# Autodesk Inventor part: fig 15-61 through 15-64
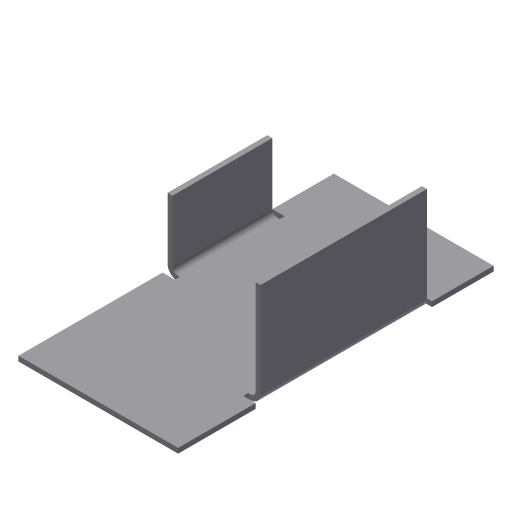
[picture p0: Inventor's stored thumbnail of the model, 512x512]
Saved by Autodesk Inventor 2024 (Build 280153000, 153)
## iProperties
Shininess: 77.0
Angle Display Precision: 2
Document Length Units: 11269
Document Angle Units: 11279
Document Time Units: 11290
Document Mass Units: 11283
Document Length Units Precision: 3
Document Angle Units Precision: 2
Compacted: True
Created: 2002-04
Part Number: fig 15-61 through 15-64
Document SubType Name: Sheet Metal
Density: 1 g/cm^3
Sheet Metal Rule: Default
Material: Generic
Appearance: Default
Density: 0.0
Volumn: 0.0
Area: 0.0
PropertySet Name: Model Information
Control State: 0
Master: False
Checked Out: False
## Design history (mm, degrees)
node "Face1"
  sketch "Sketch1"
    geometry: L1 (-33.176, 5.765)-(14.235, 5.765); L2 (14.235, 5.765)-(14.235, -18.235); L3 (14.235, -18.235)-(-33.176, -18.235); L4 (-33.176, -18.235)-(-33.176, 5.765)
    constraints: 8 end point, 2 parallel, 1 horizontal, 1 perpendicular
node "Flange1"
node "Flange2"
body "Solid1"
face "Plate1" dims "d24" = 0.75 (= Thickness)
sketch "Sketch2"
  geometry: L1 (37.412, 0)-(22.412, 0); L2 (22.412, 0)-(22.412, 10); L3 (22.412, 10)-(37.412, 10); L4 (37.412, 10)-(37.412, 0)
  constraints: 8 end point
face "Plate2" dims "d1" = 10, "d2" = 15, "d4" = 10, "d5" = 90 deg, "d6" = 0.75 (= BendRadius), "d24" = 0.75 (= Thickness), "MinimumRemnant" = 1.5 (= 2 x Thickness), "BendReliefWidth" = 0.75 (= Thickness)
bend "Bend1" dims "d3" = 0.75 (= BendRadius), "d4" = 10, "d5" = 90 deg, "d6" = 0.75 (= BendRadius), "d15" = 0.75 (= BendReliefWidth), "d16" = 0.375 (= BendReliefDepth), "d17" = 1.5 (= MinimumRemnant), "d24" = 0.75 (= Thickness), "SeamGap" = 0.01, "MinimumRemnant" = 1.5 (= 2 x Thickness), "BendReliefWidth" = 0.75 (= Thickness)
sketch "Sketch3"
  geometry: L1 (10, 0)-(35, 0); L2 (35, 0)-(35, 15); L3 (35, 15)-(10, 15); L4 (10, 15)-(10, 0)
  constraints: 8 end point
face "Plate3" dims "d7" = 10, "d8" = 25, "d10" = 15, "d11" = 90 deg, "d12" = 0.75 (= BendRadius), "d24" = 0.75 (= Thickness), "MinimumRemnant" = 1.5 (= 2 x Thickness), "BendReliefWidth" = 0.75 (= Thickness)
bend "Bend2" dims "d9" = 0.75 (= BendRadius), "d10" = 15, "d11" = 90 deg, "d12" = 0.75 (= BendRadius), "d18" = 0.75 (= BendReliefWidth), "d19" = 0.375 (= BendReliefDepth), "d20" = 1.5 (= MinimumRemnant), "d24" = 0.75 (= Thickness), "SeamGap" = 0.01, "MinimumRemnant" = 1.5 (= 2 x Thickness), "BendReliefWidth" = 0.75 (= Thickness)
other parameters: "Thickness" = 0.75, "BendRadius" = 0.75 (= Thickness), "BendReliefDepth" = 0.375 (= 0.5 x Thickness), "CornerReliefSize" = 3 (= 4 x Thickness), "TransitionRadius" = 0.75 (= BendRadius), "d0" = 0.75 (= BendRadius), "d13" = 0.75 (= BendRadius), "JacobiRadiusSize" = 0.75 (= Thickness), "GapSize" = 0.75 (= Thickness)
